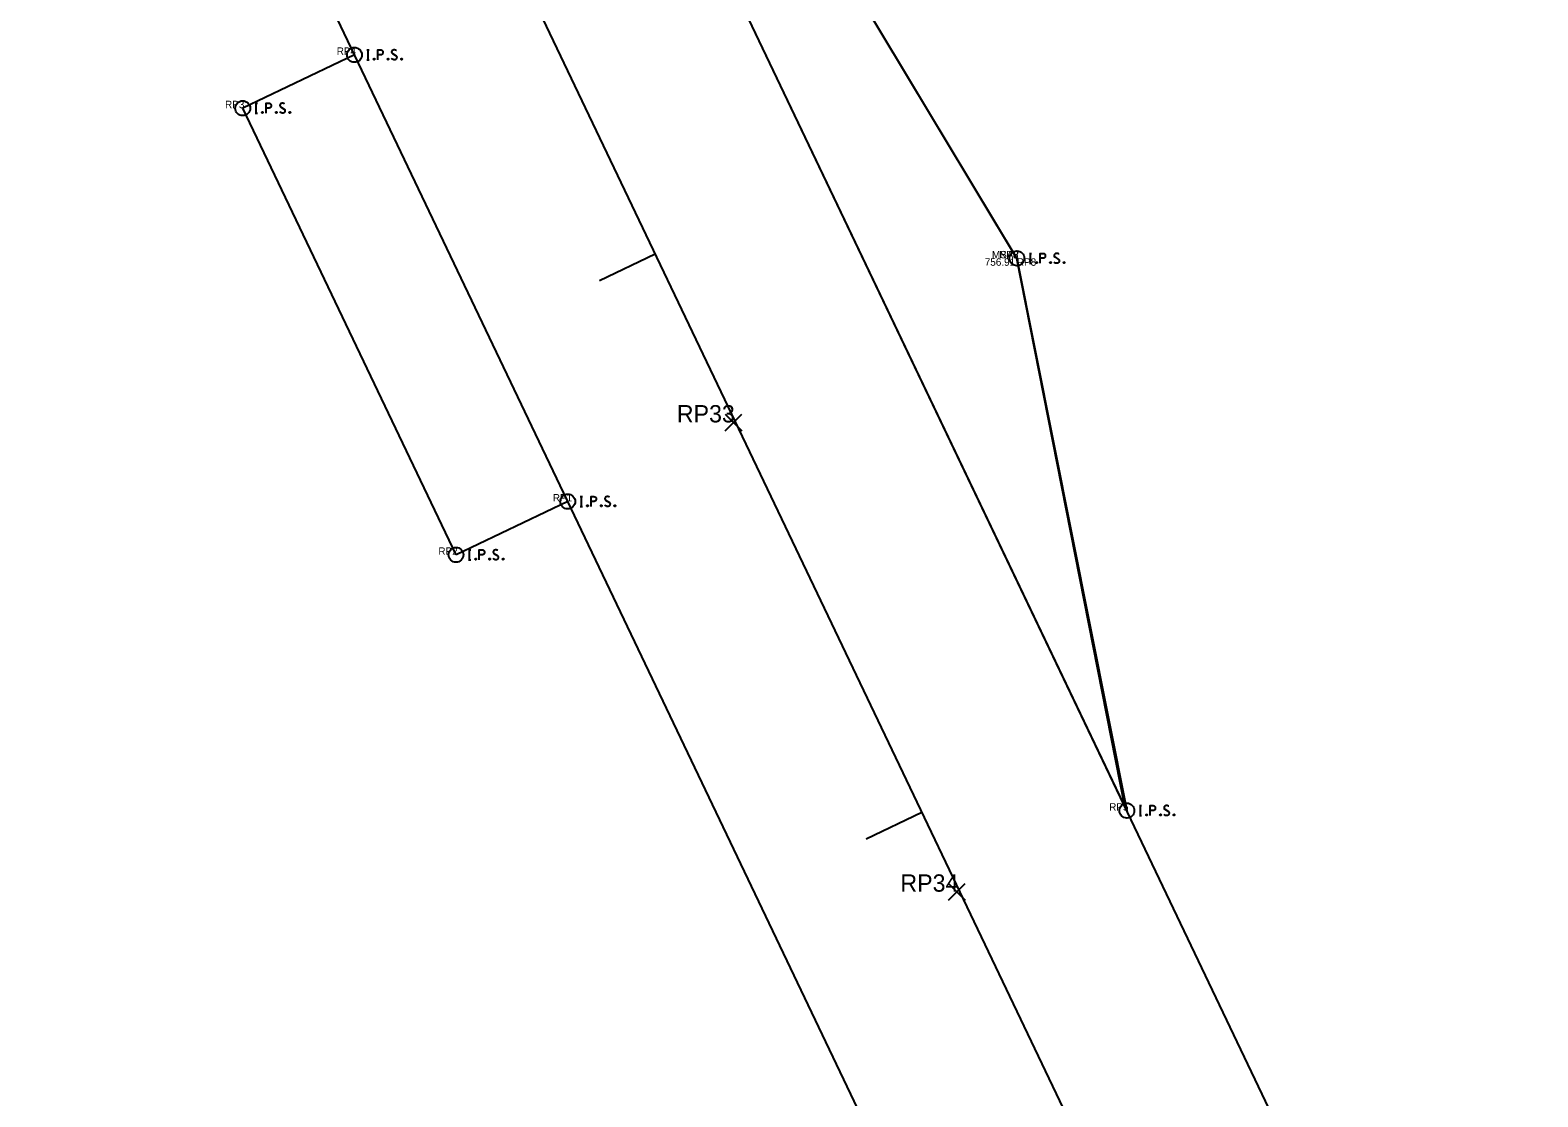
# Model space of a CAD drawing. Extents: x 2080098 to 2083965, y 589975 to 598027.
# Drawn here: x 2082726.2 to 2082969.8, y 593198.3 to 593370.7 of the extents above; entities that cross this region are included whole.
import ezdxf

# ---------------------------------------------------------------- set-up
doc = ezdxf.new("R2010")
doc.units = 0
for name, color, linetype in [('GE_X_CL_100', 7, 'Continuous'), ('GK_Visualization', 7, 'Continuous'), ('RW_P_Esmt_SH', 7, 'Continuous'), ('RW_P_Prelim_RW', 7, 'Continuous'), ('RW_X_Esmt_SH', 7, 'Continuous'), ('SV_P_Mon_Cells_Set', 7, 'Continuous'), ('SV_X_Shot_Marker', 7, 'Continuous'), ('SV_X_Text_Comment', 7, 'Continuous'), ('SV_X_Text_Elevation', 7, 'Continuous'), ('SV_X_Text_Name', 7, 'Continuous')]:
    doc.layers.add(name, color=color, linetype=linetype)

msp = doc.modelspace()

# ---------------------------------------------------------------- linework, layer by layer
at = {"layer": 'GE_X_CL_100'}
for p, q in [((2082958.18, 593060.22), (2082728.49, 593541.35)), ((2082827.24, 593334.49), (2082818.22, 593330.18)), ((2082870.32, 593244.25), (2082861.3, 593239.94))]:
    msp.add_line(p, q, dxfattribs=at)
at = {"layer": 'GK_Visualization'}
for p, q in [((2082903.43, 593244.54), (2082820.48, 593418.29)), ((2082845.53, 593400.62), (2082885.66, 593333.8)), ((2082885.66, 593333.8), (2082903.43, 593244.54)), ((2082838.54, 593305.94), (2082841.2, 593308.61)), ((2082838.54, 593308.61), (2082841.2, 593305.94)), ((2082874.63, 593230.09), (2082877.3, 593232.76)), ((2082874.63, 593232.76), (2082877.3, 593230.09))]:
    msp.add_line(p, q, dxfattribs=at)
at = {"layer": 'RW_P_Esmt_SH'}
for p, q in [((2082885.66, 593333.8), (2082845.53, 593400.62)), ((2082778.63, 593366.69), (2082760.58, 593358.07)), ((2082795.04, 593285.88), (2082760.58, 593358.07)), ((2082903.43, 593244.54), (2082885.66, 593333.8)), ((2082813.09, 593294.5), (2082795.04, 593285.88))]:
    msp.add_line(p, q, dxfattribs=at)
at = {"layer": 'RW_P_Prelim_RW'}
msp.add_lwpolyline([(2082903.1, 593245.22), (2082885.66, 593333.8), (2082845.53, 593400.62), (2082820.44, 593417.81)], dxfattribs=at)
at = {"layer": 'RW_X_Esmt_SH'}
for p, q in [((2082985.26, 593073.14), (2082755.56, 593554.27)), ((2082931.11, 593047.29), (2082701.42, 593528.42))]:
    msp.add_line(p, q, dxfattribs=at)
at = {"layer": 'SV_P_Mon_Cells_Set'}
for points in [[(2082780.65, 593367.49), (2082781, 593367.49)], [(2082780.82, 593365.89), (2082780.82, 593367.49)], [(2082782.39, 593365.89), (2082782.39, 593367.49), (2082782.92, 593367.49), (2082782.97, 593367.48), (2082783.05, 593367.45), (2082783.08, 593367.43), (2082783.11, 593367.4), (2082783.16, 593367.34), (2082783.19, 593367.28), (2082783.21, 593367.18), (2082783.21, 593367.03), (2082783.2, 593366.98), (2082783.18, 593366.9), (2082783.14, 593366.81), (2082783.09, 593366.77), (2082783.06, 593366.75), (2082783, 593366.72), (2082782.92, 593366.71), (2082782.39, 593366.71)], [(2082785.4, 593367.38), (2082785.37, 593367.4), (2082785.34, 593367.43), (2082785.24, 593367.47), (2082785.12, 593367.49), (2082785.03, 593367.49), (2082785, 593367.49), (2082784.86, 593367.45), (2082784.74, 593367.38), (2082784.66, 593367.28), (2082784.64, 593367.18), (2082784.64, 593367.1), (2082784.66, 593367), (2082784.75, 593366.91), (2082785.35, 593366.53), (2082785.41, 593366.48), (2082785.43, 593366.43), (2082785.45, 593366.36), (2082785.45, 593366.28), (2082785.44, 593366.21), (2082785.43, 593366.16), (2082785.41, 593366.09), (2082785.39, 593366.04), (2082785.36, 593366.01), (2082785.33, 593365.97), (2082785.3, 593365.94), (2082785.25, 593365.92), (2082785.22, 593365.9), (2082785.12, 593365.89), (2082784.97, 593365.89), (2082784.87, 593365.92), (2082784.72, 593366.01), (2082784.64, 593366.08)], [(2082780.65, 593365.89), (2082781, 593365.89)], [(2082781.78, 593366.11), (2082781.84, 593366.11), (2082781.87, 593366.08), (2082781.9, 593366.03), (2082781.9, 593365.97), (2082781.87, 593365.92), (2082781.84, 593365.89), (2082781.78, 593365.89), (2082781.75, 593365.92), (2082781.71, 593365.97), (2082781.71, 593366.03), (2082781.75, 593366.08), (2082781.78, 593366.11)], [(2082784.03, 593366.11), (2082784.08, 593366.11), (2082784.12, 593366.08), (2082784.15, 593366.03), (2082784.15, 593365.97), (2082784.12, 593365.92), (2082784.08, 593365.89), (2082784.03, 593365.89), (2082784, 593365.92), (2082783.96, 593365.97), (2082783.96, 593366.03), (2082784, 593366.08), (2082784.03, 593366.11)], [(2082786.21, 593366.11), (2082786.27, 593366.11), (2082786.3, 593366.08), (2082786.33, 593366.03), (2082786.33, 593365.97), (2082786.3, 593365.92), (2082786.27, 593365.89), (2082786.21, 593365.89), (2082786.18, 593365.92), (2082786.15, 593365.97), (2082786.15, 593366.03), (2082786.18, 593366.08), (2082786.21, 593366.11)], [(2082762.6, 593358.88), (2082762.95, 593358.88)], [(2082762.6, 593357.28), (2082762.95, 593357.28)], [(2082762.77, 593357.28), (2082762.77, 593358.88)], [(2082763.73, 593357.49), (2082763.79, 593357.49), (2082763.82, 593357.46), (2082763.85, 593357.41), (2082763.85, 593357.35), (2082763.82, 593357.3), (2082763.79, 593357.28), (2082763.73, 593357.28), (2082763.7, 593357.3), (2082763.67, 593357.35), (2082763.67, 593357.41), (2082763.7, 593357.46), (2082763.73, 593357.49)], [(2082764.34, 593357.28), (2082764.34, 593358.88), (2082764.87, 593358.88), (2082764.92, 593358.86), (2082765, 593358.84), (2082765.03, 593358.81), (2082765.07, 593358.79), (2082765.11, 593358.72), (2082765.14, 593358.66), (2082765.17, 593358.56), (2082765.17, 593358.41), (2082765.15, 593358.36), (2082765.13, 593358.28), (2082765.09, 593358.19), (2082765.04, 593358.16), (2082765.01, 593358.13), (2082764.96, 593358.11), (2082764.87, 593358.09), (2082764.34, 593358.09)], [(2082765.98, 593357.49), (2082766.04, 593357.49), (2082766.07, 593357.46), (2082766.1, 593357.41), (2082766.1, 593357.35), (2082766.07, 593357.3), (2082766.04, 593357.28), (2082765.98, 593357.28), (2082765.95, 593357.3), (2082765.91, 593357.35), (2082765.91, 593357.41), (2082765.95, 593357.46), (2082765.98, 593357.49)], [(2082767.35, 593358.76), (2082767.33, 593358.79), (2082767.29, 593358.81), (2082767.19, 593358.85), (2082767.07, 593358.88), (2082766.98, 593358.88), (2082766.95, 593358.88), (2082766.81, 593358.84), (2082766.69, 593358.76), (2082766.61, 593358.66), (2082766.59, 593358.56), (2082766.59, 593358.48), (2082766.61, 593358.38), (2082766.7, 593358.3), (2082767.3, 593357.92), (2082767.36, 593357.87), (2082767.38, 593357.82), (2082767.4, 593357.74), (2082767.4, 593357.67), (2082767.39, 593357.59), (2082767.38, 593357.54), (2082767.36, 593357.48), (2082767.34, 593357.43), (2082767.31, 593357.39), (2082767.28, 593357.35), (2082767.25, 593357.33), (2082767.2, 593357.3), (2082767.17, 593357.29), (2082767.07, 593357.28), (2082766.92, 593357.28), (2082766.82, 593357.3), (2082766.68, 593357.39), (2082766.59, 593357.46)], [(2082768.16, 593357.49), (2082768.22, 593357.49), (2082768.25, 593357.46), (2082768.28, 593357.41), (2082768.28, 593357.35), (2082768.25, 593357.3), (2082768.22, 593357.28), (2082768.16, 593357.28), (2082768.13, 593357.3), (2082768.1, 593357.35), (2082768.1, 593357.41), (2082768.13, 593357.46), (2082768.16, 593357.49)], [(2082887.68, 593334.6), (2082888.04, 593334.6)], [(2082887.68, 593334.6), (2082888.04, 593334.6)], [(2082887.68, 593333), (2082888.04, 593333)], [(2082887.68, 593333), (2082888.04, 593333)], [(2082887.86, 593333), (2082887.86, 593334.6)], [(2082887.86, 593333), (2082887.86, 593334.6)], [(2082888.82, 593333.21), (2082888.87, 593333.21), (2082888.91, 593333.19), (2082888.94, 593333.14), (2082888.94, 593333.08), (2082888.91, 593333.03), (2082888.87, 593333), (2082888.82, 593333), (2082888.79, 593333.03), (2082888.75, 593333.08), (2082888.75, 593333.14), (2082888.79, 593333.19), (2082888.82, 593333.21)], [(2082888.82, 593333.21), (2082888.87, 593333.21), (2082888.91, 593333.19), (2082888.94, 593333.14), (2082888.94, 593333.08), (2082888.91, 593333.03), (2082888.87, 593333), (2082888.82, 593333), (2082888.79, 593333.03), (2082888.75, 593333.08), (2082888.75, 593333.14), (2082888.79, 593333.19), (2082888.82, 593333.21)], [(2082889.42, 593333), (2082889.42, 593334.6), (2082889.95, 593334.6), (2082890.01, 593334.59), (2082890.09, 593334.56), (2082890.12, 593334.54), (2082890.15, 593334.51), (2082890.2, 593334.45), (2082890.23, 593334.39), (2082890.25, 593334.29), (2082890.25, 593334.13), (2082890.24, 593334.08), (2082890.22, 593334.01), (2082890.17, 593333.92), (2082890.13, 593333.88), (2082890.1, 593333.86), (2082890.04, 593333.83), (2082889.95, 593333.82), (2082889.42, 593333.82)], [(2082889.42, 593333), (2082889.42, 593334.6), (2082889.95, 593334.6), (2082890.01, 593334.59), (2082890.09, 593334.56), (2082890.12, 593334.54), (2082890.15, 593334.51), (2082890.2, 593334.45), (2082890.23, 593334.39), (2082890.25, 593334.29), (2082890.25, 593334.13), (2082890.24, 593334.08), (2082890.22, 593334.01), (2082890.17, 593333.92), (2082890.13, 593333.88), (2082890.1, 593333.86), (2082890.04, 593333.83), (2082889.95, 593333.82), (2082889.42, 593333.82)], [(2082891.07, 593333.21), (2082891.12, 593333.21), (2082891.16, 593333.19), (2082891.19, 593333.14), (2082891.19, 593333.08), (2082891.16, 593333.03), (2082891.12, 593333), (2082891.07, 593333), (2082891.03, 593333.03), (2082891, 593333.08), (2082891, 593333.14), (2082891.03, 593333.19), (2082891.07, 593333.21)], [(2082891.07, 593333.21), (2082891.12, 593333.21), (2082891.16, 593333.19), (2082891.19, 593333.14), (2082891.19, 593333.08), (2082891.16, 593333.03), (2082891.12, 593333), (2082891.07, 593333), (2082891.03, 593333.03), (2082891, 593333.08), (2082891, 593333.14), (2082891.03, 593333.19), (2082891.07, 593333.21)], [(2082892.43, 593334.49), (2082892.41, 593334.51), (2082892.38, 593334.54), (2082892.28, 593334.58), (2082892.16, 593334.6), (2082892.07, 593334.6), (2082892.04, 593334.6), (2082891.89, 593334.56), (2082891.77, 593334.49), (2082891.7, 593334.39), (2082891.67, 593334.29), (2082891.67, 593334.21), (2082891.7, 593334.11), (2082891.78, 593334.02), (2082892.39, 593333.64), (2082892.44, 593333.59), (2082892.47, 593333.54), (2082892.49, 593333.47), (2082892.49, 593333.39), (2082892.48, 593333.32), (2082892.47, 593333.27), (2082892.44, 593333.2), (2082892.42, 593333.15), (2082892.4, 593333.11), (2082892.37, 593333.08), (2082892.33, 593333.05), (2082892.29, 593333.03), (2082892.26, 593333.01), (2082892.16, 593333), (2082892, 593333), (2082891.9, 593333.03), (2082891.76, 593333.11), (2082891.67, 593333.19)], [(2082892.43, 593334.49), (2082892.41, 593334.51), (2082892.38, 593334.54), (2082892.28, 593334.58), (2082892.16, 593334.6), (2082892.07, 593334.6), (2082892.04, 593334.6), (2082891.89, 593334.56), (2082891.77, 593334.49), (2082891.7, 593334.39), (2082891.67, 593334.29), (2082891.67, 593334.21), (2082891.7, 593334.11), (2082891.78, 593334.02), (2082892.39, 593333.64), (2082892.44, 593333.59), (2082892.47, 593333.54), (2082892.49, 593333.47), (2082892.49, 593333.39), (2082892.48, 593333.32), (2082892.47, 593333.27), (2082892.44, 593333.2), (2082892.42, 593333.15), (2082892.4, 593333.11), (2082892.37, 593333.08), (2082892.33, 593333.05), (2082892.29, 593333.03), (2082892.26, 593333.01), (2082892.16, 593333), (2082892, 593333), (2082891.9, 593333.03), (2082891.76, 593333.11), (2082891.67, 593333.19)], [(2082893.25, 593333.21), (2082893.3, 593333.21), (2082893.34, 593333.19), (2082893.37, 593333.14), (2082893.37, 593333.08), (2082893.34, 593333.03), (2082893.3, 593333), (2082893.25, 593333), (2082893.22, 593333.03), (2082893.18, 593333.08), (2082893.18, 593333.14), (2082893.22, 593333.19), (2082893.25, 593333.21)], [(2082893.25, 593333.21), (2082893.3, 593333.21), (2082893.34, 593333.19), (2082893.37, 593333.14), (2082893.37, 593333.08), (2082893.34, 593333.03), (2082893.3, 593333), (2082893.25, 593333), (2082893.22, 593333.03), (2082893.18, 593333.08), (2082893.18, 593333.14), (2082893.22, 593333.19), (2082893.25, 593333.21)], [(2082815.11, 593295.3), (2082815.46, 593295.3)], [(2082815.11, 593293.7), (2082815.46, 593293.7)], [(2082815.29, 593293.7), (2082815.29, 593295.3)], [(2082816.25, 593293.91), (2082816.3, 593293.91), (2082816.34, 593293.89), (2082816.37, 593293.84), (2082816.37, 593293.77), (2082816.34, 593293.72), (2082816.3, 593293.7), (2082816.25, 593293.7), (2082816.21, 593293.72), (2082816.18, 593293.77), (2082816.18, 593293.84), (2082816.21, 593293.89), (2082816.25, 593293.91)], [(2082816.85, 593293.7), (2082816.85, 593295.3), (2082817.38, 593295.3), (2082817.44, 593295.28), (2082817.51, 593295.26), (2082817.55, 593295.23), (2082817.58, 593295.21), (2082817.62, 593295.15), (2082817.66, 593295.08), (2082817.68, 593294.98), (2082817.68, 593294.83), (2082817.67, 593294.78), (2082817.65, 593294.7), (2082817.6, 593294.62), (2082817.56, 593294.58), (2082817.53, 593294.55), (2082817.47, 593294.53), (2082817.38, 593294.52), (2082816.85, 593294.52)], [(2082818.5, 593293.91), (2082818.55, 593293.91), (2082818.58, 593293.89), (2082818.62, 593293.84), (2082818.62, 593293.77), (2082818.58, 593293.72), (2082818.55, 593293.7), (2082818.5, 593293.7), (2082818.46, 593293.72), (2082818.43, 593293.77), (2082818.43, 593293.84), (2082818.46, 593293.89), (2082818.5, 593293.91)], [(2082819.86, 593295.18), (2082819.84, 593295.21), (2082819.81, 593295.23), (2082819.71, 593295.27), (2082819.59, 593295.3), (2082819.5, 593295.3), (2082819.47, 593295.3), (2082819.32, 593295.26), (2082819.2, 593295.18), (2082819.12, 593295.08), (2082819.1, 593294.98), (2082819.1, 593294.91), (2082819.12, 593294.81), (2082819.21, 593294.72), (2082819.82, 593294.34), (2082819.87, 593294.29), (2082819.9, 593294.24), (2082819.92, 593294.16), (2082819.92, 593294.09), (2082819.91, 593294.01), (2082819.9, 593293.96), (2082819.87, 593293.9), (2082819.85, 593293.85), (2082819.83, 593293.81), (2082819.8, 593293.77), (2082819.76, 593293.75), (2082819.72, 593293.72), (2082819.69, 593293.71), (2082819.59, 593293.7), (2082819.43, 593293.7), (2082819.33, 593293.72), (2082819.19, 593293.81), (2082819.1, 593293.89)], [(2082820.68, 593293.91), (2082820.73, 593293.91), (2082820.77, 593293.89), (2082820.8, 593293.84), (2082820.8, 593293.77), (2082820.77, 593293.72), (2082820.73, 593293.7), (2082820.68, 593293.7), (2082820.65, 593293.72), (2082820.61, 593293.77), (2082820.61, 593293.84), (2082820.65, 593293.89), (2082820.68, 593293.91)], [(2082797.06, 593286.68), (2082797.42, 593286.68)], [(2082797.24, 593285.08), (2082797.24, 593286.68)], [(2082798.8, 593285.08), (2082798.8, 593286.68), (2082799.33, 593286.68), (2082799.39, 593286.67), (2082799.47, 593286.64), (2082799.5, 593286.62), (2082799.53, 593286.59), (2082799.58, 593286.53), (2082799.61, 593286.47), (2082799.63, 593286.37), (2082799.63, 593286.21), (2082799.62, 593286.16), (2082799.6, 593286.09), (2082799.55, 593286), (2082799.51, 593285.96), (2082799.48, 593285.94), (2082799.42, 593285.91), (2082799.33, 593285.9), (2082798.8, 593285.9)], [(2082801.81, 593286.57), (2082801.79, 593286.59), (2082801.76, 593286.62), (2082801.66, 593286.66), (2082801.54, 593286.68), (2082801.45, 593286.68), (2082801.42, 593286.68), (2082801.27, 593286.64), (2082801.15, 593286.57), (2082801.08, 593286.47), (2082801.05, 593286.37), (2082801.05, 593286.29), (2082801.08, 593286.19), (2082801.16, 593286.1), (2082801.77, 593285.72), (2082801.82, 593285.67), (2082801.85, 593285.62), (2082801.87, 593285.55), (2082801.87, 593285.47), (2082801.86, 593285.4), (2082801.85, 593285.35), (2082801.82, 593285.28), (2082801.8, 593285.23), (2082801.78, 593285.19), (2082801.75, 593285.16), (2082801.71, 593285.13), (2082801.67, 593285.11), (2082801.64, 593285.09), (2082801.54, 593285.08), (2082801.38, 593285.08), (2082801.28, 593285.11), (2082801.14, 593285.19), (2082801.05, 593285.27)], [(2082797.06, 593285.08), (2082797.42, 593285.08)], [(2082798.2, 593285.29), (2082798.25, 593285.29), (2082798.29, 593285.27), (2082798.32, 593285.22), (2082798.32, 593285.16), (2082798.29, 593285.11), (2082798.25, 593285.08), (2082798.2, 593285.08), (2082798.17, 593285.11), (2082798.13, 593285.16), (2082798.13, 593285.22), (2082798.17, 593285.27), (2082798.2, 593285.29)], [(2082800.45, 593285.29), (2082800.5, 593285.29), (2082800.54, 593285.27), (2082800.57, 593285.22), (2082800.57, 593285.16), (2082800.54, 593285.11), (2082800.5, 593285.08), (2082800.45, 593285.08), (2082800.41, 593285.11), (2082800.38, 593285.16), (2082800.38, 593285.22), (2082800.41, 593285.27), (2082800.45, 593285.29)], [(2082802.63, 593285.29), (2082802.68, 593285.29), (2082802.72, 593285.27), (2082802.75, 593285.22), (2082802.75, 593285.16), (2082802.72, 593285.11), (2082802.68, 593285.08), (2082802.63, 593285.08), (2082802.6, 593285.11), (2082802.56, 593285.16), (2082802.56, 593285.22), (2082802.6, 593285.27), (2082802.63, 593285.29)], [(2082905.45, 593245.34), (2082905.8, 593245.34)], [(2082905.62, 593243.74), (2082905.62, 593245.34)], [(2082907.19, 593243.74), (2082907.19, 593245.34), (2082907.72, 593245.34), (2082907.77, 593245.33), (2082907.85, 593245.3), (2082907.88, 593245.28), (2082907.92, 593245.25), (2082907.96, 593245.19), (2082907.99, 593245.13), (2082908.02, 593245.03), (2082908.02, 593244.88), (2082908, 593244.83), (2082907.98, 593244.75), (2082907.94, 593244.66), (2082907.89, 593244.62), (2082907.86, 593244.6), (2082907.81, 593244.57), (2082907.72, 593244.56), (2082907.19, 593244.56)], [(2082910.2, 593245.23), (2082910.18, 593245.25), (2082910.14, 593245.28), (2082910.04, 593245.32), (2082909.92, 593245.34), (2082909.83, 593245.34), (2082909.8, 593245.34), (2082909.66, 593245.3), (2082909.54, 593245.23), (2082909.46, 593245.13), (2082909.44, 593245.03), (2082909.44, 593244.95), (2082909.46, 593244.85), (2082909.55, 593244.76), (2082910.15, 593244.38), (2082910.21, 593244.33), (2082910.23, 593244.28), (2082910.25, 593244.21), (2082910.25, 593244.13), (2082910.24, 593244.06), (2082910.23, 593244.01), (2082910.21, 593243.94), (2082910.19, 593243.89), (2082910.16, 593243.86), (2082910.13, 593243.82), (2082910.1, 593243.79), (2082910.05, 593243.77), (2082910.02, 593243.75), (2082909.92, 593243.74), (2082909.77, 593243.74), (2082909.67, 593243.77), (2082909.53, 593243.86), (2082909.44, 593243.93)], [(2082905.45, 593243.74), (2082905.8, 593243.74)], [(2082906.58, 593243.96), (2082906.64, 593243.96), (2082906.67, 593243.93), (2082906.7, 593243.88), (2082906.7, 593243.82), (2082906.67, 593243.77), (2082906.64, 593243.74), (2082906.58, 593243.74), (2082906.55, 593243.77), (2082906.52, 593243.82), (2082906.52, 593243.88), (2082906.55, 593243.93), (2082906.58, 593243.96)], [(2082908.83, 593243.96), (2082908.89, 593243.96), (2082908.92, 593243.93), (2082908.95, 593243.88), (2082908.95, 593243.82), (2082908.92, 593243.77), (2082908.89, 593243.74), (2082908.83, 593243.74), (2082908.8, 593243.77), (2082908.77, 593243.82), (2082908.77, 593243.88), (2082908.8, 593243.93), (2082908.83, 593243.96)], [(2082911.01, 593243.96), (2082911.07, 593243.96), (2082911.1, 593243.93), (2082911.13, 593243.88), (2082911.13, 593243.82), (2082911.1, 593243.77), (2082911.07, 593243.74), (2082911.01, 593243.74), (2082910.98, 593243.77), (2082910.95, 593243.82), (2082910.95, 593243.88), (2082910.98, 593243.93), (2082911.01, 593243.96)]]:
    msp.add_lwpolyline(points, dxfattribs=at)
for centre in [(2082778.63, 593366.69), (2082760.58, 593358.07), (2082885.66, 593333.8), (2082885.66, 593333.8), (2082813.09, 593294.5), (2082795.04, 593285.88), (2082903.43, 593244.54)]:
    msp.add_circle(centre, 1.2, dxfattribs=at)
at = {"layer": 'SV_X_Shot_Marker'}
for p, q in [((2082903.08, 593245.22), (2082903.13, 593245.22)), ((2082903.1, 593245.25), (2082903.1, 593245.2)), ((2082903.1, 593245.22), (2082903.1, 593245.22))]:
    msp.add_line(p, q, dxfattribs=at)

# ---------------------------------------------------------------- texts
at = {"layer": 'GK_Visualization'}
for s, p in [('RP33', (2082830.72, 593307.28)), ('RP34', (2082866.84, 593231.43))]:
    msp.add_text(s, height=2.8, dxfattribs=at).set_placement(p)
at = {"layer": 'SV_X_Text_Comment'}
for s, height, p in [('RP8', 0.06, (2082885.66, 593333.74)), ('RP8', 1.2, (2082885.66, 593332.6)), ('TAPER FROM EX R/W', 0.06, (2082903.1, 593245.16))]:
    msp.add_text(s, height=height, dxfattribs=at).set_placement(p)
at = {"layer": 'SV_X_Text_Elevation'}
for s, height, p in [('756.91', 1.2, (2082880.47, 593332.6)), ('756.91', 0.06, (2082885.4, 593333.74)), ('755.74', 0.06, (2082902.82, 593245.16))]:
    msp.add_text(s, height=height, dxfattribs=at).set_placement(p)
at = {"layer": 'SV_X_Text_Name'}
for s, height, p in [('RP4', 1.2, (2082775.77, 593366.69)), ('RP3', 1.2, (2082757.72, 593358.07)), ('MSA2', 1.2, (2082881.62, 593333.8)), ('RP8', 1.2, (2082882.79, 593333.8)), ('MSA2', 0.06, (2082885.46, 593333.8)), ('RP1', 1.2, (2082810.68, 593294.5)), ('RP2', 1.2, (2082792.19, 593285.88)), ('RP5', 1.2, (2082900.57, 593244.54)), ('MSA1', 0.06, (2082902.92, 593245.22)), ('RP5', 0.06, (2082903.29, 593244.54))]:
    msp.add_text(s, height=height, dxfattribs=at).set_placement(p)

doc.saveas('drawing.dxf')
